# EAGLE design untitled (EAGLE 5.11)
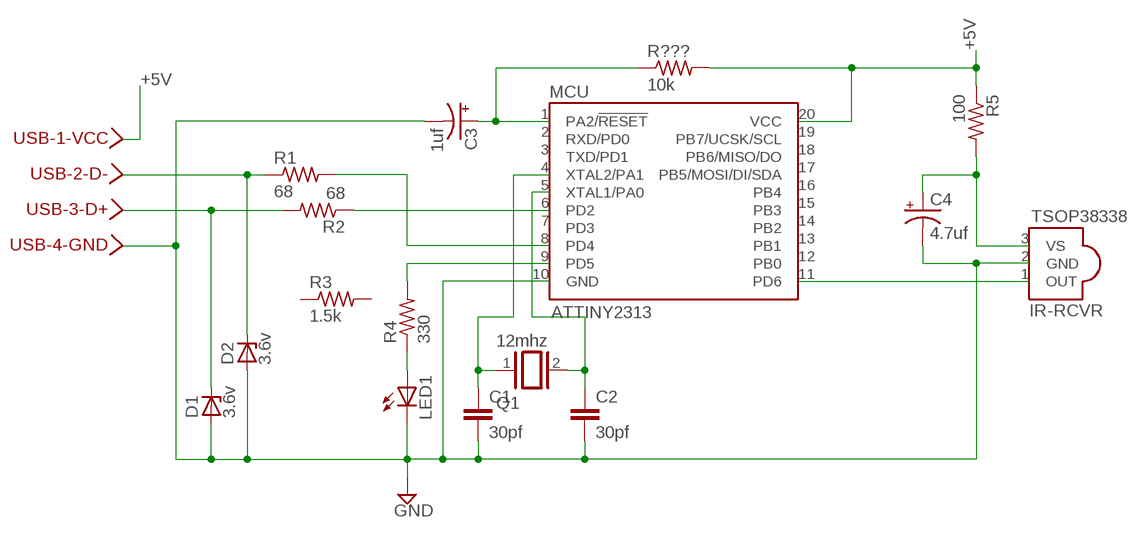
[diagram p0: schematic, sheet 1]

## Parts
C1  30pf  C-EU050-024X044  [C050-024X044]
C2  30pf  C-EU050-024X044  [C050-024X044]
C3  1uf  CPOL-USE2-4  [E2-4]
C4  4.7uf  CPOL-USE2-4  [E2-4]
D1  3.6v  ZENER-DIODEZD-7.5  [ZDIO-7.5]
D2  3.6v  ZENER-DIODEZD-7.5  [ZDIO-7.5]
IR-RCVR  TSOP38338  [TSOP38338]
LED1  LED5MM  [LED5MM]
MCU  ATTINY2313  [DIL20]
Q1  12mhz  XTAL/S  [QS]
R1  68  R-US_0207/10  [0207/10]
R2  68  R-US_0207/10  [0207/10]
R3  1.5k  R-US_0207/10  [0207/10]
R4  330  R-US_0207/10  [0207/10]
R5  100  R-US_0207/10  [0207/10]
R???  10k  R-US_0207/10  [0207/10]
USB-1-VCC  WIREPAD-SMD-SMALL-NAMED  [WIREPAD-SMD-SMALL]
USB-2-D-  WIREPAD-SMD-SMALL-NAMED  [WIREPAD-SMD-SMALL]
USB-3-D+  WIREPAD-SMD-SMALL-NAMED  [WIREPAD-SMD-SMALL]
USB-4-GND  WIREPAD-SMD-SMALL-NAMED  [WIREPAD-SMD-SMALL]

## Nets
+5V: MCU.20(VCC) R5.1 R???.2 USB-1-VCC.1
GND: C1.2 C2.2 C3.- C4.- D1.A D2.A IR-RCVR.2(GND) LED1.K(C) MCU.10(GND) USB-4-GND.1
N$1: MCU.9(PD5) R4.2
N$2: LED1.A R4.1
N$3: IR-RCVR.1(OUT) MCU.11(PD6)
N$4: C4.+ IR-RCVR.3(VS) R5.2
N$5: MCU.6(PD2) R2.1
N$6: D1.C R2.2 USB-3-D+.1
N$7: D2.C R1.1 USB-2-D-.1
N$8: C1.1 MCU.4(XTAL2/PA1) Q1.1
N$9: MCU.8(PD4) R1.2
N$11: C2.1 MCU.5(XTAL1/PA0) Q1.2
N$12: C3.+ MCU.1(PA2/!RESET) R???.1
Unconnected: MCU.2(RXD/PD0) MCU.3(TXD/PD1) MCU.7(PD3) MCU.12(PB0) MCU.13(PB1) MCU.14(PB2) MCU.15(PB3) MCU.16(PB4) MCU.17(PB5/MOSI/DI/SDA) MCU.18(PB6/MISO/DO) MCU.19(PB7/UCSK/SCL) R3.1 R3.2

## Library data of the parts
C1 C2 = rcl:C-EU: CAPACITOR, European symbol
C3 C4 = rcl:CPOL-US: POLARIZED CAPACITOR, American symbol
D1 D2 = diode:ZENER-DIODE: Z-Diode
IR-RCVR = trl:TSOP38338
LED1 = led:LED: LED
MCU = trl:ATTINY2313
Q1 = special:XTAL/S: CRYSTAL
R1-R5 R??? = resistor:R-US_: RESISTOR, American symbol
USB-1-VCC USB-2-D- USB-3-D+ USB-4-GND = trl:WIREPAD-SMD-SMALL-NAMED

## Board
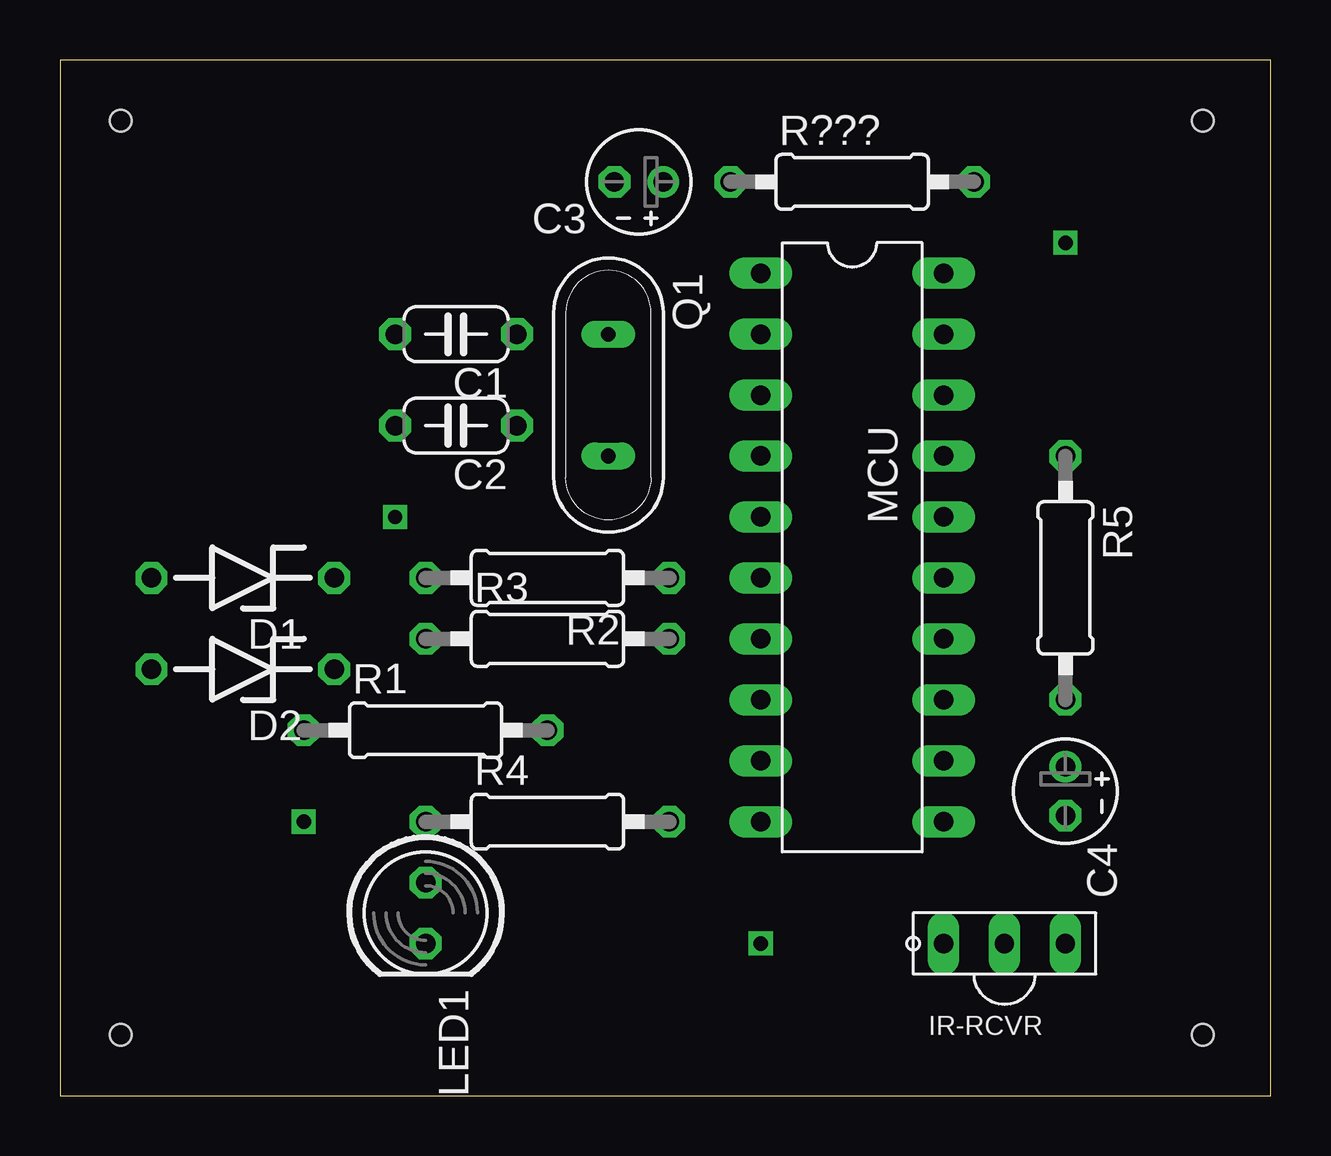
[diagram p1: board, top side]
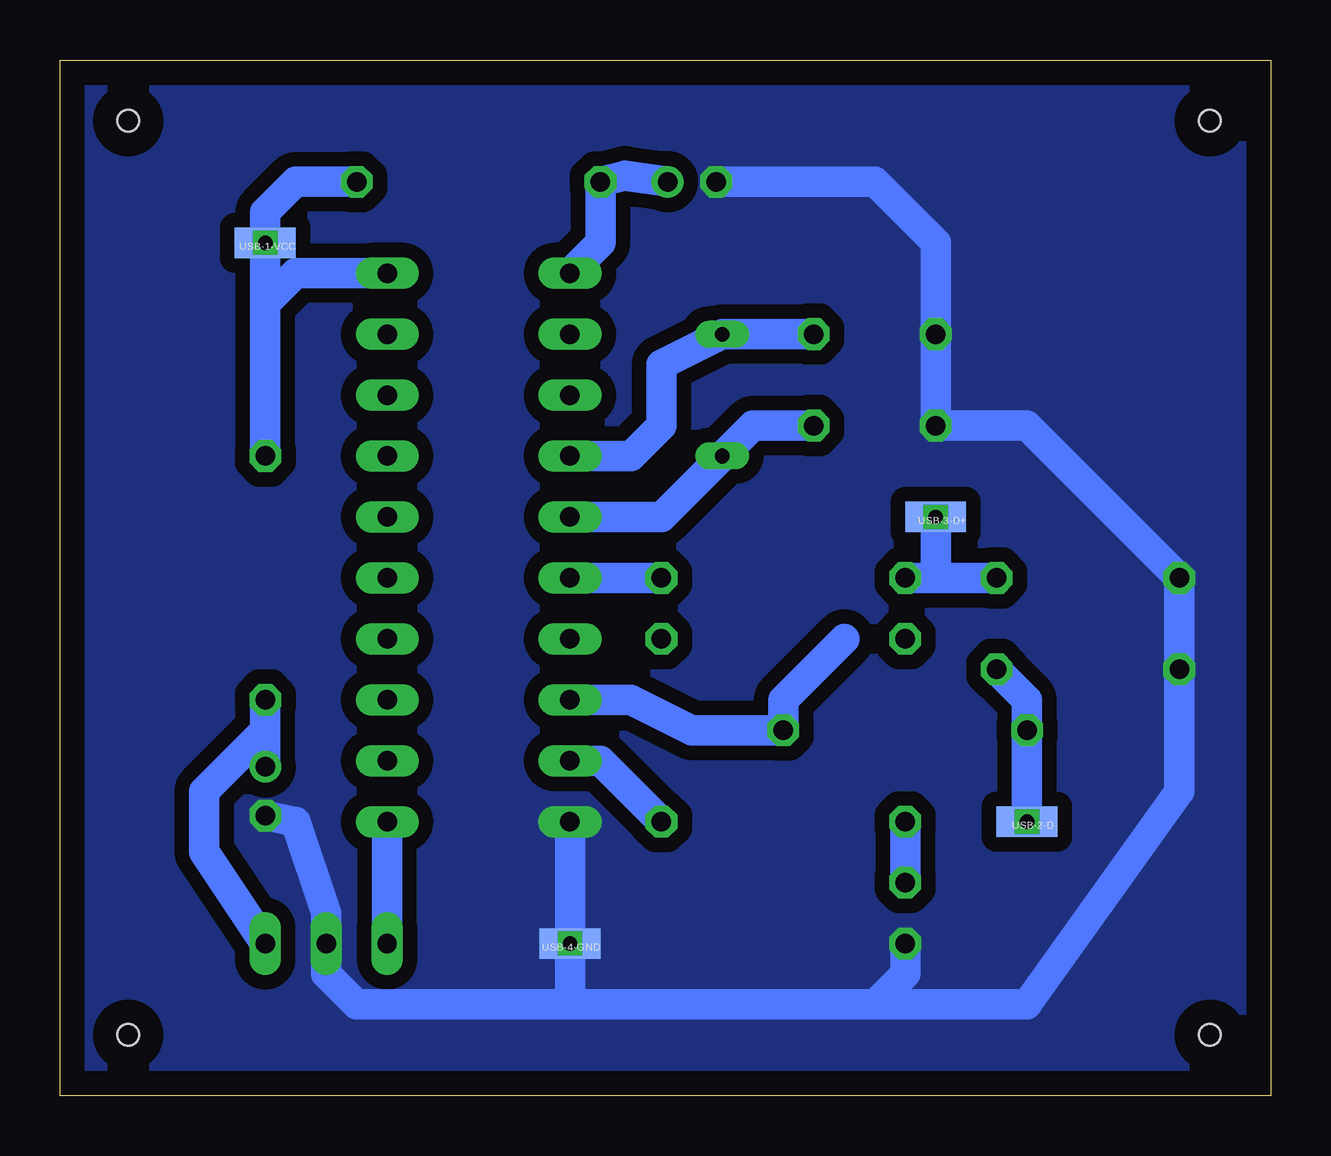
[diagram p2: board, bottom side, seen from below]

Size 50.47 x 43.18 mm. Coordinates in mm from the lower left corner, seen from the top.
Outline: 0,0 50.47,0 50.47,43.17 0.01,43.18 0,0
Copper layers (1*16): Top 0.035mm / dielectric 1.5mm / Bottom 0.035mm
Design rules "default": minimum track width 10mil, minimum drill 24mil, track to track 8mil, track to pad 8mil, pad to pad 8mil, via to via 8mil, smd to smd 8mil, copper to edge 40mil, drill to drill 8mil, minimum pad ring 10mil, minimum via ring 8mil, stop-mask expansion 4mil, vias tented up to drill 0mil, thermal gap 10mil
Holes 0.9 mm at 2.54,40.64 47.62,40.64 2.54,2.54 47.62,2.54

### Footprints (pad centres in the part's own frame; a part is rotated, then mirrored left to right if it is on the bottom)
C050-024X044 = drill 0.813 octagon: 1 -2.54,0; 2 2.54,0
E2-4 = drill 0.813 pad 1.27 round: + -1.016,0 | drill 0.813 pad 1.27 octagon: - 1.016,0
ZDIO-7.5 = drill 0.813 octagon: A 3.81,0; C -3.81,0
TSOP38338 = drill 0.8 long: 1 -2.54,0; 2 0,0; 3 2.54,0
LED5MM = drill 0.813 octagon: A -1.27,0; K 1.27,0
DIL20 = drill 0.813 long: 1 -11.43,-3.81; 2 -8.89,-3.81; 3 -6.35,-3.81; 4 -3.81,-3.81; 5 -1.27,-3.81; 6 1.27,-3.81; 7 3.81,-3.81; 8 6.35,-3.81; 9 8.89,-3.81; 10 11.43,-3.81; 11 11.43,3.81; 12 8.89,3.81; 13 6.35,3.81; 14 3.81,3.81; 15 1.27,3.81; 16 -1.27,3.81; 17 -3.81,3.81; 18 -6.35,3.81; 19 -8.89,3.81; 20 -11.43,3.81
QS = drill 0.61 long: 1 -2.54,0; 2 2.54,0
0207/10 = drill 0.813 octagon: 1 -5.08,0; 2 5.08,0
WIREPAD-SMD-SMALL = smd 2.54 x 1.27: 1 0,0

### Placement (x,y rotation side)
C1  16.51,31.75 180 top
C2  16.51,27.94 180 top
C3  24.13,38.1 180 top
C4  41.91,12.7 270 top
D1  7.62,21.59 180 top
D2  7.62,17.78 180 top
IR-RCVR  39.37,6.35 0 top
LED1  15.24,7.62 270 top
MCU  33.02,22.86 270 top
Q1  22.86,29.21 270 top
R1  15.24,15.24 0 top
R2  20.32,21.59 180 top
R3  20.32,19.05 0 top
R4  20.32,11.43 0 top
R5  41.91,21.59 270 top
R???  33.02,38.1 0 top
USB-1-VCC  41.91,35.56 180 bottom
USB-2-D-  10.16,11.43 180 bottom
USB-3-D+  13.97,24.13 180 bottom
USB-4-GND  29.21,6.35 180 bottom

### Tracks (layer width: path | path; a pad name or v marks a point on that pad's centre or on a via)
+5V  (via drill 0.6)
  Bottom 1.27: R5.1 41.91,33.02 | 41.91,33.02 40.64,34.29 MCU.20 | 41.91,33.02 USB-1-VCC.1 41.91,36.83 40.64,38.1 R???.2
  other vias: 41.91,35.56
GND  (via drill 0.6)
  Bottom 1.27: 16.51,3.81 10.16,3.81 3.81,12.7 D2.A D1.A 10.16,27.94 C2.2 C1.2 13.97,35.56 16.51,38.1 C3.- | 16.51,3.81 29.21,3.81 | 29.21,3.81 38.1,3.81 39.37,5.08 IR-RCVR.2 39.37,7.62 40.64,11.43 C4.- | MCU.10 USB-4-GND.1 29.21,3.81 | LED1.K 15.24,5.08 16.51,3.81
  other vias: 29.21,6.35
  pour Bottom (isolate 0.61, no thermals): 0,43.18 50.8,43.18 50.8,0 0,0
N$1
  Bottom 1.27: R4.2 27.94,13.97 MCU.9
N$2
  Bottom 1.27: LED1.A R4.1
N$3
  Bottom 1.27: IR-RCVR.1 MCU.11
N$4
  Bottom 1.27: IR-RCVR.3 44.45,10.16 44.45,12.7 41.91,15.24 R5.2 C4.+
N$5
  Bottom 1.27: R2.1 MCU.6
N$6  (via drill 0.6)
  Bottom 1.27: D1.C 13.97,21.59 | 13.97,21.59 USB-3-D+.1 | 13.97,21.59 R2.2
  other vias: 13.97,24.13
N$7  (via drill 0.6)
  Bottom 1.27: D2.C 10.16,16.51 R1.1 USB-2-D-.1
  other vias: 10.16,11.43
N$8
  Bottom 1.27: MCU.4 26.67,26.67 25.4,27.94 25.4,30.48 Q1.1 C1.1
N$9
  Bottom 1.27: MCU.8 26.67,16.51 24.13,15.24 R1.2 20.32,16.51 17.78,19.05
N$11
  Bottom 1.27: C2.1 21.59,27.94 Q1.2 25.4,24.13 MCU.5
N$12
  Bottom 1.27: C3.+ 26.92,38.35 R???.1 27.94,35.56 MCU.1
